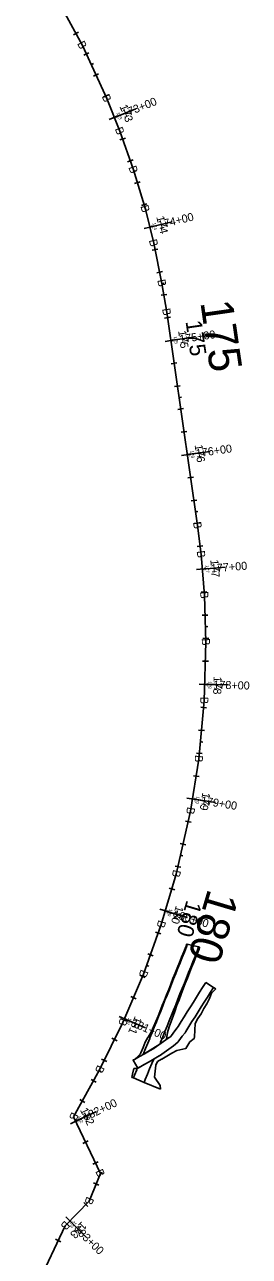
# Model space of a CAD drawing. Extents: x 1823824 to 1861612, y 706975 to 726130.
# Drawn here: x 1826622 to 1826817, y 713518 to 714585 of the extents above; entities that cross this region are included whole.
import ezdxf

# ---------------------------------------------------------------- set-up
doc = ezdxf.new("R2010")
doc.units = 0
for name, color, linetype in [('DR_X_Flood_Boundary', 7, 'Continuous'), ('GE_X_CL_10', 7, 'Continuous'), ('GE_X_CL_100', 7, 'Continuous'), ('GE_X_CL_20', 7, 'Continuous'), ('GE_X_CL_200', 7, 'Continuous'), ('GE_X_CL_50', 7, 'Continuous'), ('SC_Scratch1', 7, 'Continuous'), ('SC_Scratch5', 7, 'Continuous'), ('SC_Scratch6', 7, 'Continuous')]:
    doc.layers.add(name, color=color, linetype=linetype)

msp = doc.modelspace()

# ---------------------------------------------------------------- linework, layer by layer
at = {"layer": 'DR_X_Flood_Boundary'}
for p, q in [((1826650.1, 714607.3), (1826671.9, 714567.1)), ((1826671.9, 714567.1), (1826693.2, 714521.1)), ((1826693.2, 714521.1), (1826704.4, 714492.8)), ((1826704.4, 714492.8), (1826716.2, 714459.2)), ((1826716.2, 714459.2), (1826726.5, 714425.2)), ((1826726.5, 714425.2), (1826733.7, 714395.6)), ((1826733.7, 714395.6), (1826740.9, 714360.8)), ((1826740.9, 714360.8), (1826745, 714335.8)), ((1826745, 714335.8), (1826771.7, 714150.9)), ((1826771.7, 714150.9), (1826774.9, 714125.8)), ((1826774.9, 714125.8), (1826777.7, 714090.4)), ((1826777.7, 714090.4), (1826779, 714049.8)), ((1826779, 714049.8), (1826777.6, 713999)), ((1826777.6, 713999), (1826772.9, 713948.5)), ((1826772.9, 713948.5), (1826765.7, 713903.4)), ((1826765.7, 713903.4), (1826753.3, 713848.9)), ((1826753.3, 713848.9), (1826740.3, 713805.2)), ((1826740.3, 713805.2), (1826724.8, 713762.3)), ((1826724.8, 713762.3), (1826707, 713720.3)), ((1826707, 713720.3), (1826686.8, 713679.3)), ((1826686.8, 713679.3), (1826664.3, 713638.4)), ((1826664.3, 713638.4), (1826687.6, 713589.5)), ((1826687.6, 713589.5), (1826677.7, 713565.4)), ((1826677.7, 713565.4), (1826656.9, 713544.1)), ((1826656.9, 713544.1), (1826621.8, 713470))]:
    msp.add_line(p, q, dxfattribs=at)
at = {"layer": 'GE_X_CL_10'}
for p, q in [((1826679.6, 714550.5), (1826680.5, 714550.9)), ((1826699.7, 714504.7), (1826700.6, 714505.1)), ((1826716.6, 714457.7), (1826717.6, 714458)), ((1826730.3, 714409.6), (1826731.3, 714409.8)), ((1826740.9, 714360.7), (1826741.9, 714360.9)), ((1826748.5, 714311.3), (1826749.5, 714311.5)), ((1826755.7, 714261.8), (1826756.7, 714262)), ((1826762.8, 714212.4), (1826763.8, 714212.5)), ((1826770, 714162.9), (1826771, 714163)), ((1826775.9, 714113.2), (1826776.9, 714113.3)), ((1826778.6, 714063.3), (1826779.6, 714063.4)), ((1826778, 714013.3), (1826779, 714013.3)), ((1826774.3, 713963.5), (1826775.3, 713963.4)), ((1826767.4, 713914), (1826768.4, 713913.8)), ((1826757, 713865.1), (1826758, 713864.9)), ((1826743.8, 713816.9), (1826744.7, 713816.6)), ((1826727.5, 713769.7), (1826728.4, 713769.3)), ((1826708.3, 713723.5), (1826709.3, 713723.1)), ((1826686.4, 713678.6), (1826687.3, 713678.1)), ((1826666.1, 713634.7), (1826667, 713635.1)), ((1826687.6, 713589.5), (1826688.5, 713590)), ((1826661, 713548.3), (1826661.7, 713547.6))]:
    msp.add_line(p, q, dxfattribs=at)
at = {"layer": 'GE_X_CL_100'}
for p, q in [((1826699.7, 714504.7), (1826709, 714508.4)), ((1826730.3, 714409.6), (1826740, 714412)), ((1826748.5, 714311.3), (1826758.4, 714312.8)), ((1826762.8, 714212.4), (1826772.7, 714213.8)), ((1826775.9, 714113.2), (1826785.8, 714114)), ((1826778, 714013.3), (1826788, 714013.1)), ((1826767.4, 713914), (1826777.3, 713912.4)), ((1826743.8, 713816.9), (1826753.4, 713814.1)), ((1826708.3, 713723.5), (1826717.5, 713719.6)), ((1826666.1, 713634.7), (1826675.1, 713639)), ((1826661, 713548.3), (1826668.1, 713541.3))]:
    msp.add_line(p, q, dxfattribs=at)
at = {"layer": 'GE_X_CL_20'}
for p, q in [((1826679.6, 714550.5), (1826681.4, 714551.3)), ((1826699.7, 714504.7), (1826701.5, 714505.4)), ((1826716.6, 714457.7), (1826718.6, 714458.3)), ((1826730.3, 714409.6), (1826732.3, 714410.1)), ((1826740.9, 714360.7), (1826742.9, 714361.1)), ((1826748.5, 714311.3), (1826750.5, 714311.6)), ((1826755.7, 714261.8), (1826757.7, 714262.1)), ((1826762.8, 714212.4), (1826764.8, 714212.6)), ((1826770, 714162.9), (1826772, 714163.2)), ((1826775.9, 714113.2), (1826777.9, 714113.4)), ((1826778.6, 714063.3), (1826780.6, 714063.4)), ((1826778, 714013.3), (1826780, 714013.3)), ((1826774.3, 713963.5), (1826776.3, 713963.3)), ((1826767.4, 713914), (1826769.4, 713913.7)), ((1826757, 713865.1), (1826759, 713864.7)), ((1826743.8, 713816.9), (1826745.7, 713816.3)), ((1826727.5, 713769.7), (1826729.4, 713769)), ((1826708.3, 713723.5), (1826710.2, 713722.7)), ((1826686.4, 713678.6), (1826688.2, 713677.6)), ((1826666.1, 713634.7), (1826667.9, 713635.5)), ((1826687.6, 713589.5), (1826689.4, 713590.4)), ((1826661, 713548.3), (1826662.4, 713546.9))]:
    msp.add_line(p, q, dxfattribs=at)
at = {"layer": 'GE_X_CL_200'}
for p, q in [((1826699.7, 714504.7), (1826718.3, 714512.1)), ((1826730.3, 714409.6), (1826749.8, 714414.3)), ((1826748.5, 714311.3), (1826768.3, 714314.2)), ((1826762.8, 714212.4), (1826782.6, 714215.2)), ((1826775.9, 714113.2), (1826795.8, 714114.8)), ((1826778, 714013.3), (1826798, 714012.8)), ((1826767.4, 713914), (1826787.2, 713910.9)), ((1826743.8, 713816.9), (1826763, 713811.2)), ((1826708.3, 713723.5), (1826726.7, 713715.7)), ((1826666.1, 713634.7), (1826684.1, 713643.3)), ((1826661, 713548.3), (1826675.3, 713534.3))]:
    msp.add_line(p, q, dxfattribs=at)
at = {"layer": 'GE_X_CL_50'}
for p, q in [((1826699.7, 714504.7), (1826704.3, 714506.6)), ((1826730.3, 714409.6), (1826735.2, 714410.8)), ((1826748.5, 714311.3), (1826753.5, 714312.1)), ((1826762.8, 714212.4), (1826767.8, 714213.1)), ((1826775.9, 714113.2), (1826780.8, 714113.6)), ((1826778, 714013.3), (1826783, 714013.2)), ((1826767.4, 713914), (1826772.4, 713913.2)), ((1826743.8, 713816.9), (1826748.6, 713815.5)), ((1826708.3, 713723.5), (1826712.9, 713721.5)), ((1826666.1, 713634.7), (1826670.6, 713636.8)), ((1826661, 713548.3), (1826664.6, 713544.8))]:
    msp.add_line(p, q, dxfattribs=at)
at = {"layer": 'SC_Scratch1'}
for p, q in [((1826724.5, 713692.5), (1826739, 713701.5)), ((1826739, 713701.5), (1826740, 713702.2)), ((1826744.7, 713706), (1826748.2, 713707.9)), ((1826724.5, 713692.5), (1826724, 713692.2)), ((1826716.5, 713680.3), (1826719.9, 713680.6)), ((1826733.7, 713688.5), (1826719.5, 713680.4)), ((1826719.5, 713680.4), (1826719.9, 713680.6)), ((1826733.7, 713688.5), (1826734, 713688.7))]:
    msp.add_line(p, q, dxfattribs=at)
for points in [[(1826762.3, 713788.2), (1826761.9, 713786.3), (1826761.7, 713786), (1826759.8, 713781.4), (1826757.9, 713776.8), (1826756, 713772.2), (1826754.2, 713767.5), (1826752.3, 713762.9), (1826750.4, 713758.3), (1826748.6, 713753.6), (1826746.7, 713749), (1826744.9, 713744.3), (1826743, 713739.7), (1826741.2, 713735), (1826739.3, 713730.4), (1826737.5, 713725.8), (1826735.6, 713721.1), (1826733.6, 713716.5), (1826731.5, 713712), (1826728.9, 713707.6), (1826728.6, 713707.2), (1826726.4, 713703.3), (1826724.5, 713698.7), (1826722.6, 713694.1), (1826722.2, 713693.3), (1826722, 713692.9)], [(1826724.5, 713692.5), (1826726.7, 713697.8), (1826728.6, 713702.4), (1826730.3, 713706.5), (1826730.5, 713707), (1826732.3, 713711.6), (1826734.2, 713716.3), (1826736.1, 713720.9), (1826737.9, 713725.6), (1826739.8, 713730.2), (1826741.7, 713734.8), (1826743.5, 713739.5), (1826745.4, 713744.1), (1826747.3, 713748.8), (1826749.1, 713753.4), (1826751, 713758), (1826752.9, 713762.7), (1826754.7, 713767.3), (1826756.6, 713772), (1826758.5, 713776.6), (1826760.3, 713781.2), (1826762.2, 713785.9), (1826762.4, 713786.1), (1826762.8, 713788.1)], [(1826772.6, 713785.8), (1826772.1, 713783.9), (1826771.5, 713782.1), (1826769.6, 713777.5), (1826767.7, 713772.9), (1826765.9, 713768.2), (1826764, 713763.6), (1826762.1, 713758.9), (1826760.3, 713754.3), (1826758.4, 713749.7), (1826756.5, 713745), (1826754.7, 713740.4), (1826752.8, 713735.7), (1826750.9, 713731.1), (1826749.1, 713726.5), (1826747.2, 713721.8), (1826745.3, 713717.2), (1826743.5, 713712.6), (1826741.6, 713707.9), (1826739.7, 713703.3), (1826739.5, 713702.8), (1826739, 713701.5)], [(1826744.7, 713706), (1826745.8, 713711.6), (1826747, 713716.5), (1826748.8, 713721.2), (1826750.5, 713725.9), (1826752.2, 713730.6), (1826753.9, 713735.3), (1826755.7, 713740), (1826757.4, 713744.7), (1826759.2, 713749.4), (1826761.1, 713754), (1826763, 713758.6), (1826764.8, 713763.3), (1826766.6, 713767.9), (1826768.5, 713772.6), (1826770.2, 713777.2), (1826772.4, 713781.8), (1826773.2, 713783.6), (1826773.3, 713785.6)], [(1826773.3, 713785.6), (1826772.6, 713785.8), (1826762.8, 713788.1), (1826762.3, 713788.2)], [(1826778.8, 713755), (1826776.1, 713750.7), (1826773.5, 713746.5), (1826770.8, 713742.3), (1826768.2, 713738), (1826765.5, 713733.8), (1826762.8, 713729.6), (1826760.2, 713725.3), (1826757.5, 713721.1), (1826754.8, 713716.9), (1826754.1, 713715.7), (1826752.1, 713713.1), (1826749.1, 713709.1), (1826748.2, 713707.9), (1826746.3, 713706.7), (1826742.2, 713703.8), (1826738.1, 713700.9), (1826734, 713698), (1826733.9, 713697.8), (1826730.1, 713695.7), (1826725.7, 713693.2), (1826721.4, 713690.7), (1826717, 713688.2), (1826715.9, 713687.6)], [(1826787.6, 713749.4), (1826785.6, 713750.7), (1826778.8, 713755)], [(1826719.9, 713680.6), (1826721, 713681.3), (1826725.4, 713683.8), (1826729.7, 713686.2), (1826734, 713688.7), (1826738.5, 713691.3), (1826738.7, 713691.5), (1826742.8, 713694.4), (1826746.8, 713697.3), (1826750.9, 713700.2), (1826754.6, 713703.1), (1826755.5, 713704.3), (1826758.5, 713708.3), (1826760.9, 713711.4), (1826761.6, 713712.6), (1826764.3, 713716.8), (1826766.9, 713721.1), (1826769.6, 713725.3), (1826772.3, 713729.5), (1826774.9, 713733.8), (1826777.6, 713738), (1826780.3, 713742.2), (1826782.9, 713746.5), (1826785.6, 713750.7)], [(1826787.6, 713749.4), (1826783.9, 713745.8), (1826782.1, 713741.1), (1826779.9, 713736.6), (1826777.3, 713732.3), (1826774.9, 713727.9), (1826772, 713723.8), (1826769.8, 713719.3), (1826769.5, 713713.6), (1826769.1, 713707.9), (1826768.8, 713706.4), (1826765, 713703.4), (1826762.4, 713699.1), (1826761.6, 713697.8), (1826753.9, 713696), (1826749.4, 713693.7), (1826745.1, 713691.1), (1826740.8, 713688.6), (1826740.6, 713688.4), (1826736.9, 713686.4)], [(1826715.8, 713687.8), (1826717, 713688.3), (1826720.8, 713691.8), (1826722, 713692.9)], [(1826719.5, 713680.4), (1826716.5, 713680.3), (1826715.4, 713675.4), (1826714.8, 713672.7)], [(1826715.8, 713687.8), (1826715.9, 713687.6), (1826719.9, 713680.6)], [(1826716.2, 713672.2), (1826717.2, 713674.7), (1826719.1, 713679.3), (1826719.5, 713680.4)], [(1826733.7, 713688.5), (1826732.1, 713684.7), (1826730.2, 713680.1), (1826728.3, 713675.5), (1826726.4, 713670.9), (1826725.4, 713668.4)], [(1826739.7, 713662.5), (1826739.2, 713665.6), (1826734.4, 713673), (1826735.1, 713678.1), (1826735.5, 713683.3), (1826736.9, 713686.4)], [(1826739.7, 713662.5), (1826725.4, 713668.4), (1826716.2, 713672.2), (1826714.8, 713672.7)]]:
    msp.add_lwpolyline(points, dxfattribs=at)
at = {"layer": 'SC_Scratch5'}
for points in [[(1826668.5, 714578.6), (1826664.1, 714576.2)], [(1826677.6, 714560.6), (1826673.1, 714558.5)], [(1826686, 714542.4), (1826681.5, 714540.3)], [(1826694.4, 714524.3), (1826689.9, 714522.2)], [(1826704.3, 714506.6), (1826695, 714502.9)], [(1826709.2, 714486.8), (1826704.4, 714485.2)], [(1826715.8, 714468), (1826711, 714466.3)], [(1826721.9, 714448.8), (1826717.2, 714447.4)], [(1826727.8, 714429.7), (1826723, 714428.3)], [(1826735.2, 714410.8), (1826725.5, 714408.4)], [(1826737.3, 714390.6), (1826732.4, 714389.6)], [(1826741.3, 714371), (1826736.4, 714370)], [(1826745, 714351.3), (1826740.1, 714350.5)], [(1826748.2, 714331.5), (1826743.2, 714330.8)], [(1826753.5, 714312.1), (1826743.6, 714310.6)], [(1826753.9, 714291.9), (1826748.9, 714291.2)], [(1826756.7, 714272.1), (1826751.8, 714271.4)], [(1826759.6, 714252.3), (1826754.7, 714251.6)], [(1826762.5, 714232.5), (1826757.5, 714231.8)], [(1826767.8, 714213.1), (1826757.9, 714211.6)], [(1826768.2, 714192.9), (1826763.2, 714192.2)], [(1826771, 714173.1), (1826766.1, 714172.4)], [(1826773.9, 714153.3), (1826768.9, 714152.6)], [(1826776.4, 714133.5), (1826771.5, 714132.8)], [(1826780.8, 714113.6), (1826770.9, 714112.8)], [(1826779.9, 714093.5), (1826774.9, 714093.1)], [(1826780.7, 714073.4), (1826775.7, 714073.2)], [(1826781.4, 714053.4), (1826776.4, 714053.2)], [(1826781.1, 714033.3), (1826776.1, 714033.4)], [(1826783, 714013.2), (1826773, 714013.5)], [(1826779.6, 713993.1), (1826774.6, 713993.6)], [(1826777.7, 713973.2), (1826772.7, 713973.7)], [(1826775.8, 713953.3), (1826770.9, 713953.8)], [(1826773, 713933.4), (1826768.1, 713934.1)], [(1826772.4, 713913.2), (1826762.5, 713914.8)], [(1826766.1, 713893.8), (1826761.2, 713894.9)], [(1826761.7, 713874.3), (1826756.8, 713875.4)], [(1826757.2, 713854.8), (1826752.4, 713855.9)], [(1826751.9, 713835.4), (1826747.1, 713836.8)], [(1826748.6, 713815.5), (1826739, 713818.4)], [(1826740, 713797), (1826735.3, 713798.7)], [(1826733.2, 713778.2), (1826728.5, 713779.9)], [(1826726.3, 713759.3), (1826721.7, 713761.3)], [(1826718.5, 713740.9), (1826713.9, 713742.9)], [(1826712.9, 713721.5), (1826703.7, 713725.4)], [(1826701.9, 713704.4), (1826697.4, 713706.6)], [(1826693.1, 713686.4), (1826688.6, 713688.6)], [(1826683.8, 713668.6), (1826679.4, 713671)], [(1826674.1, 713651.1), (1826669.7, 713653.5)], [(1826670.6, 713636.8), (1826661.6, 713632.5)], [(1826676.9, 713617.7), (1826672.4, 713615.5)], [(1826685.5, 713599.6), (1826681, 713597.5)], [(1826686.1, 713579.3), (1826681.5, 713581.2)], [(1826676.7, 713560.8), (1826673.2, 713564.3)], [(1826664.6, 713544.8), (1826657.4, 713551.8)], [(1826653.1, 713530.2), (1826648.6, 713532.4)]]:
    msp.add_lwpolyline(points, dxfattribs=at)

# ---------------------------------------------------------------- texts
at = {"layer": 'GE_X_CL_10'}
for s, rotation, p in [('173', 291.7481, (1826700.5, 714506.6)), ('174', 283.7166, (1826731.4, 714411.4)), ('175', 278.2202, (1826749.8, 714313)), ('176', 278.2202, (1826764.1, 714214)), ('177', 274.5054, (1826777.2, 714114.8)), ('178', 268.4521, (1826779.6, 714014.7)), ('179', 261.0001, (1826769.1, 713915.2)), ('180', 253.3828, (1826745.7, 713817.9)), ('181', 246.9935, (1826710.2, 713724)), ('182', 295.4895, (1826666.8, 713636.6)), ('183', 225.7025, (1826663.1, 713548.3))]:
    msp.add_text(s, height=1.4, rotation=rotation, dxfattribs=at).set_placement(p)
at = {"layer": 'GE_X_CL_100'}
for s, rotation, p in [('175', 278.2202, (1826761.3, 714327.9)), ('180', 253.3828, (1826762.4, 713826.9))]:
    msp.add_text(s, height=14, rotation=rotation, dxfattribs=at).set_placement(p)
at = {"layer": 'GE_X_CL_20'}
for s, rotation, p in [('173', 291.7481, (1826701.4, 714508.5)), ('174', 283.7166, (1826732.6, 714413.1)), ('175', 278.2202, (1826751.1, 714314.7)), ('176', 278.2202, (1826765.4, 714215.7)), ('177', 274.5054, (1826778.6, 714116.4)), ('178', 268.4521, (1826781.1, 714016.1)), ('179', 261.0001, (1826770.8, 713916.4)), ('180', 253.3828, (1826747.5, 713818.9)), ('181', 246.9935, (1826712.1, 713724.6)), ('182', 295.4895, (1826667.5, 713638.6)), ('183', 225.7025, (1826665.2, 713548.3))]:
    msp.add_text(s, height=2.8, rotation=rotation, dxfattribs=at).set_placement(p)
at = {"layer": 'GE_X_CL_200'}
for s, rotation, p in [('175', 278.2202, (1826774.1, 714344.5)), ('180', 253.3828, (1826781.1, 713837))]:
    msp.add_text(s, height=28, rotation=rotation, dxfattribs=at).set_placement(p)
at = {"layer": 'GE_X_CL_50'}
for s, rotation, p in [('173', 291.7481, (1826703.9, 714514.3)), ('174', 283.7166, (1826735.9, 714418.4)), ('175', 278.2202, (1826754.9, 714319.6)), ('176', 278.2202, (1826769.2, 714220.7)), ('177', 274.5054, (1826782.8, 714121.3)), ('178', 268.4521, (1826785.7, 714020.3)), ('179', 261.0001, (1826776, 713920)), ('180', 253.3828, (1826753.1, 713821.9)), ('181', 246.9935, (1826717.6, 713726.2)), ('182', 295.4895, (1826669.7, 713644.5)), ('183', 225.7025, (1826671.5, 713548.3))]:
    msp.add_text(s, height=7, rotation=rotation, dxfattribs=at).set_placement(p)
at = {"layer": 'SC_Scratch5'}
for s, rotation, p in [('173+00', 21.7481, (1826707.9, 714504.2)), ('174+00', 13.7166, (1826738.4, 714408)), ('175+00', 8.2202, (1826756.5, 714308.9)), ('176+00', 8.2202, (1826770.8, 714210)), ('177+00', 4.5054, (1826783.6, 714110.3)), ('178+00', 358.4521, (1826785.4, 714009.6)), ('179+00', 351.0001, (1826774.3, 713909.4)), ('180+00', 343.3828, (1826750, 713811.4)), ('181+00', 336.9935, (1826713.9, 713717.3)), ('182+00', 25.4895, (1826674.3, 713634.7)), ('183+00', 315.7025, (1826663.9, 713540.5))]:
    msp.add_text(s, height=7, rotation=rotation, dxfattribs=at).set_placement(p)
at = {"layer": 'SC_Scratch6'}
for rotation, p in [(298.432, (1826667.1, 714568.6)), (294.8042, (1826688.5, 714522.8)), (291.7481, (1826699.9, 714494.7)), (289.2651, (1826711.7, 714461.4)), (286.928, (1826722.1, 714427.6)), (283.7166, (1826729.5, 714398.2)), (281.6163, (1826736.8, 714363.6)), (279.3498, (1826741, 714338.7)), (278.2202, (1826767.8, 714153.9)), (277.148, (1826771, 714128.8)), (274.5054, (1826773.9, 714093.6)), (271.882, (1826775.4, 714053.1)), (268.4521, (1826774.2, 714002.6)), (264.6274, (1826769.7, 713952.3)), (261.0001, (1826762.8, 713907.4)), (257.1805, (1826750.7, 713853.1)), (253.3828, (1826737.9, 713809.5)), (250.1645, (1826722.7, 713766.7)), (246.9935, (1826705.1, 713724.8)), (243.8213, (1826685.2, 713684)), (241.1266, (1826662.9, 713643.2)), (295.4895, (1826682.9, 713591.2)), (247.6594, (1826675.8, 713569.9)), (225.7025, (1826656.8, 713549))]:
    msp.add_text('B', height=7, rotation=rotation, dxfattribs=at).set_placement(p)

doc.saveas('drawing.dxf')
